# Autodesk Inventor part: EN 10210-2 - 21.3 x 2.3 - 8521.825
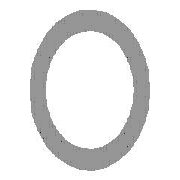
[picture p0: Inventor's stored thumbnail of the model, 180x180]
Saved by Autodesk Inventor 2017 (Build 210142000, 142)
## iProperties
Created: 2016-02
Part Number: EN 10210-2 - 21.3 x 2.3 - 8521.825
Material: Steel, Mild
Description: Pipe
Document SubType Name: Modeling
Standard: DIN
Designer: iusti
Standard Revision: 2006-07
Standards Organization: DIN
Language: en-US
Size Designation: 21.3 x 2.3
Categories: <MemberInstance><Categories><Category DisplayName="Structural Shapes" InternalName="089c4875-fa83-4c05-b084-43b9cc11f5ed" Mnemonic="GRDR"><CategoryParameter Dis
Stock Number: 21.3 x 2.3
Density: 7.85 g/cm^3
Appearance: Semi-Polished
_CCFamilyMember: 1
_CCFamilyDisplayName: DIN EN 10210-2 - Pipe
_FrameMemberDoc: Frame Member File
_Version: 15.0.0
_GetPNFromCC: 1
G_L: 8518.706 mm
G_W: 21.300 mm
G_H: 21.300 mm
+22488682-7980-44F7-8CC4-272C3B725D64+CUTDETAIL1: Miter 45.00 deg
+80B2A45B-F442-4791-9C48-37951358E670+CUTDETAIL2: Miter 45.00 deg
+6A921974-C6F6-4C2B-935D-6313A8222D38+CUTDETAIL3: Miter 45.00 deg
IsCustomPart: 1
Author: iusti
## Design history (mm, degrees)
node "Start plane"
node "End plane"
sketch "Sketch"
  geometry: C1 r 8.35 at (0, 0); C2 r 10.65 at (0, 0); 2 further points
  constraints: 3 coincident, 2 centre point
  dimensions: "d0" = 21.3 diameter of C2 (= G_H); "d1" = 2.3 radial gap between concentric circles of C2 C1 (= G_T)
extrude "Body" new body sketch "Sketch" stored distance "d2" = 8518.70561 (= G_L); taper "d3" = 0 deg
node "Driven Length"
  sketch "Sketch3"
    geometry: L1 (0, 0)-(10, 0) reference
    constraints: 2 end point, 1 horizontal
  workplane "Work Plane3"
  sketch "Sketch4"
    geometry: L1 (-2, -10.65)-(12, -10.65) reference; L2 (-2, 8511.175)-(12, 8511.175) reference
    dimensions: "d7" = 8521.82492 distance between parallel lines of L1 L2 (derived)
workplane "Work Plane4"
split "Split1"
workplane "Work Plane5"
split "Split2"
workplane "Work Plane6"
split "Split3"
body "Solid1"
other parameters: "G_H" = 21.3 [user parameter; used in 1 equation term], "G_T" = 2.3 [user parameter; used in 1 equation term], "G_L" = 8518.70561 [user parameter; used in 1 equation term], "G_OFFSET_START" = 10.65 [user parameter; used in 1 equation term], "G_OFFSET_END" = 10.65 [user parameter; used in 1 equation term], "d4" = -10.65 (= -G_OFFSET_START), "d5" = 8511.17492 (= G_OFFSET_END + B_L), "B_L" = 8500.52492 [user parameter; used in 1 equation term], "d6" = 90 deg
